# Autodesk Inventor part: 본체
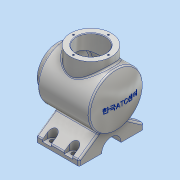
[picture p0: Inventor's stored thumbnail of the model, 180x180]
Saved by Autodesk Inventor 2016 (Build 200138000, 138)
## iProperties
Created: 2017-04
Part Number: 본체
Material: 알루미늄 6061
Document SubType Name: Modeling
Designer: 201-06
Density: 2.7 g/cm^3
Appearance: 알루미늄 - 평지
Mass: 1664.55 g
Surface Area: 1066.84 cm^2
Volume: 616.5 cm^3
Author: 201-06
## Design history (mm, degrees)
sketch "스케치1"
  geometry: L1 (62, 82)-(62, 120); L2 (0, 147)-(-38, 147); L3 (-38, 147)-(-38, 96.947); L4 (-38, 96.947)-(0, 96.947); L5 (0, 96.947)-(0, 147); L6 (53, 120)-(62, 120); L7 (62, 120)-(62, 82); L8 (62, 82)-(-58, 82); L9 (47, 132)-(-44.454, 132); L10 (50, 123)-(50, 129); A1 r 113 centre (55, 82) between (-47.166, 130.282) and (-58, 82); A2 r 3 centre (53, 123) between (50, 123) and (53, 120); A3 r 3 centre (47, 129) between (50, 129) and (47, 132); A4 r 3 centre (-44.454, 129) between (-44.454, 132) and (-47.166, 130.282); 3 further points
  constraints: 20 end point, 9 point on circle, 6 tangent, 4 centre point, 2 equal radius, 2 horizontal, 2 parallel, 2 perpendicular, 1 point on line, 1 vertical alignment
  dimensions: "d1" = 82 vertical distance of point (0, 0) L8.end; "d2" = 147 distance from line of point (0, 0) L2; "d3" = 38 distance of L2.start L2.end; "d9" = 3 radius of A2; "d97" = 12 distance between parallel lines of L10 L1; "d98" = 50 distance from line of L10 L2.start; "d102" = 108 distance from line of L8.end L10
revolve "회전1" stored, may be unused: angle "d10" = 90 deg
revolve "회전2" stored, may be unused: angle "d11" = 90 deg
node "작업 평면1"
node "작업 평면3"
sketch "스케치10"
  geometry: L1 (-82, 60)-(-82, 18); L2 (-82, -18)-(-82, -60); L3 (-72, 60)-(-29.988, 0); L4 (-72, -60)-(-29.988, 0); L5 (-82, -60)-(-72, -60); L6 (-82, 60)-(-72, 60); A1 r 18 centre (-82, 0) between (-82, -18) and (-82, 18); 2 further points
  constraints: 12 end point, 2 point on circle, 1 centre point, 1 coincident, 1 horizontal, 1 parallel
  dimensions: "d114" = 10 distance of L2.end L4.start
extrude "돌출3" join sketch "스케치10" distance "d105" = 80; taper "d106" = 0 deg
sketch "스케치3"
  geometry: L1 (-30, 60)-(-30, 50); L2 (-14, 60)-(-14, 50); L3 (10, 50)-(10, 60); L4 (26, 50)-(26, 60); L5 (-30, -60)-(-30, -50); L6 (-14, -60)-(-14, -50); L7 (10, -50)-(10, -60); L8 (26, -50)-(26, -60); L9 (-30, 60)-(-14, 60); L10 (10, 60)-(26, 60); L11 (26, -60)-(10, -60); L12 (-14, -60)-(-30, -60); A1 r 8 centre (-22, 50) between (-30, 50) and (-14, 50); A2 r 8 centre (18, 50) between (10, 50) and (26, 50); A3 r 8 centre (18, -50) between (26, -50) and (10, -50); A4 r 8 centre (-22, -50) between (-14, -50) and (-30, -50); 2 further points
  constraints: 24 end point, 8 point on circle, 4 centre point
extrude "돌출2" cut sketch "스케치3" stored distance "d37" = 80; taper "d38" = 0 deg
sketch "스케치4"
  geometry: L1 (-42, 60)-(38, 60) reference; L2 (-42, 18)-(-42, 60) reference; 4 further points
hole "구멍1" sketch "스케치4" at (-22, 50), (18, 50), (18, -50), (-22, -50) diameter "d43" = 8; stored, may be unused: countersink angle "d47" = 90 deg, drill point angle "d49" = 118 deg; dims "d44" = 6, "d45" = 4, "d46" = 2, "d48" = 8
sketch "스케치5"
  geometry: L1 (38, 147)-(-38, 147) reference; L2 (0, 147)-(-27, 147); L3 (-27, 147)-(-27, 88.38); L4 (-27, 88.38)-(0, 88.38); L5 (0, 88.38)-(0, 147); 1 further point
  constraints: 8 end point, 2 parallel, 1 horizontal, 1 midpoint, 1 perpendicular
  dimensions: "d50" = 27 distance of L4.end L3.end
revolve "회전3" sketch "스케치5" stored, may be unused: angle "d51" = 90 deg
sketch "스케치6"
  geometry: L1 (-37.903, 122)-(37, 122); L2 (-48, 82)-(62, 82); L3 (-48, 109)-(-44.398, 109); L4 (40, 109)-(62, 109); L5 (40, 109)-(40, 119); L6 (62, 109)-(62, 82); L7 (50, 35)-(50, 129) reference; L8 (-44.454, 132)-(47, 132) reference; A1 r 103 centre (55, 82) between (-40.69, 120.11) and (-48, 82); A2 r 3 centre (37, 119) between (40, 119) and (37, 122); A3 r 3 centre (-37.903, 45) between (-40.69, 43.89) and (-37.903, 42); A4 r 3 centre (-37.903, 119) between (-37.903, 122) and (-40.69, 120.11); A5 r 113 centre (55, 82) between (-47.166, 130.282) and (-47.166, 33.718) reference; 1 further point
  constraints: 12 end point, 9 point on circle, 5 tangent, 4 centre point, 2 parallel, 1 horizontal, 1 perpendicular
  dimensions: "d56" = 3 radius of A2; "d99" = 10 distance between parallel lines of L1 L8; "d100" = 10 distance between parallel lines of L7 L5; "d101" = 10 radial gap between concentric circles of A5 A1
revolve "회전4" sketch "스케치6" stored, may be unused: angle "d58" = 90 deg
chamfer "모따기1" distance "d59" = 1; stored, may be unused: second distance "d60" = 2, angle "d61" = 45 deg
fillet "모깎기1" dims "d62" = 3
chamfer "모따기2" distance "d66" = 1; stored, may be unused: second distance "d67" = 2, angle "d68" = 45 deg
sketch "스케치7"
  geometry: 5 further points
  constraints: 5 other
  dimensions: "d72" = 360 deg dimension on point (0, 0) point (0, -32.5) (derived)
sketch "스케치8"
  geometry: 6 further points
  constraints: 5 other
  dimensions: "d77" = 360 deg dimension on point (0, 0) point (0, 32.5) (derived)
hole "구멍2" sketch "스케치7" diameter "d79" = 3.242; stored, may be unused: countersink angle "d83" = 90 deg, drill point angle "d85" = 118 deg; dims "d80" = 8, "d81" = 4, "d82" = 2, "d84" = 10
hole "구멍3" sketch "스케치8" diameter "d86" = 3.242; stored, may be unused: countersink angle "d90" = 90 deg, drill point angle "d92" = 118 deg; dims "d87" = 8, "d88" = 4, "d89" = 2, "d91" = 10
node "작업 평면2"
sketch "스케치9"
  geometry: L1 (-33.183, 86.803)-(33.183, 86.803); L2 (33.183, 86.803)-(33.183, 77.197); L3 (33.183, 77.197)-(-33.183, 77.197); L4 (-33.183, 77.197)-(-33.183, 86.803); C1 r 48.282 at (0, 82) reference; 2 further points
  constraints: 2 other
feature "엠보싱1" sketch "스케치9" dims "d1" = 82, "d2" = 147, "d3" = 38, "d9" = 3, "d94" = 0.5, "d95" = 0, "d97" = 12, "d98" = 50, "d102" = 108
fillet "모깎기5" dims "d107" = 3
fillet "모깎기6" dims "d108" = 3
node "솔리드1"
other parameters: "d18" = 6, "d31" = 10, "d57" = 27, "d103" = -8
